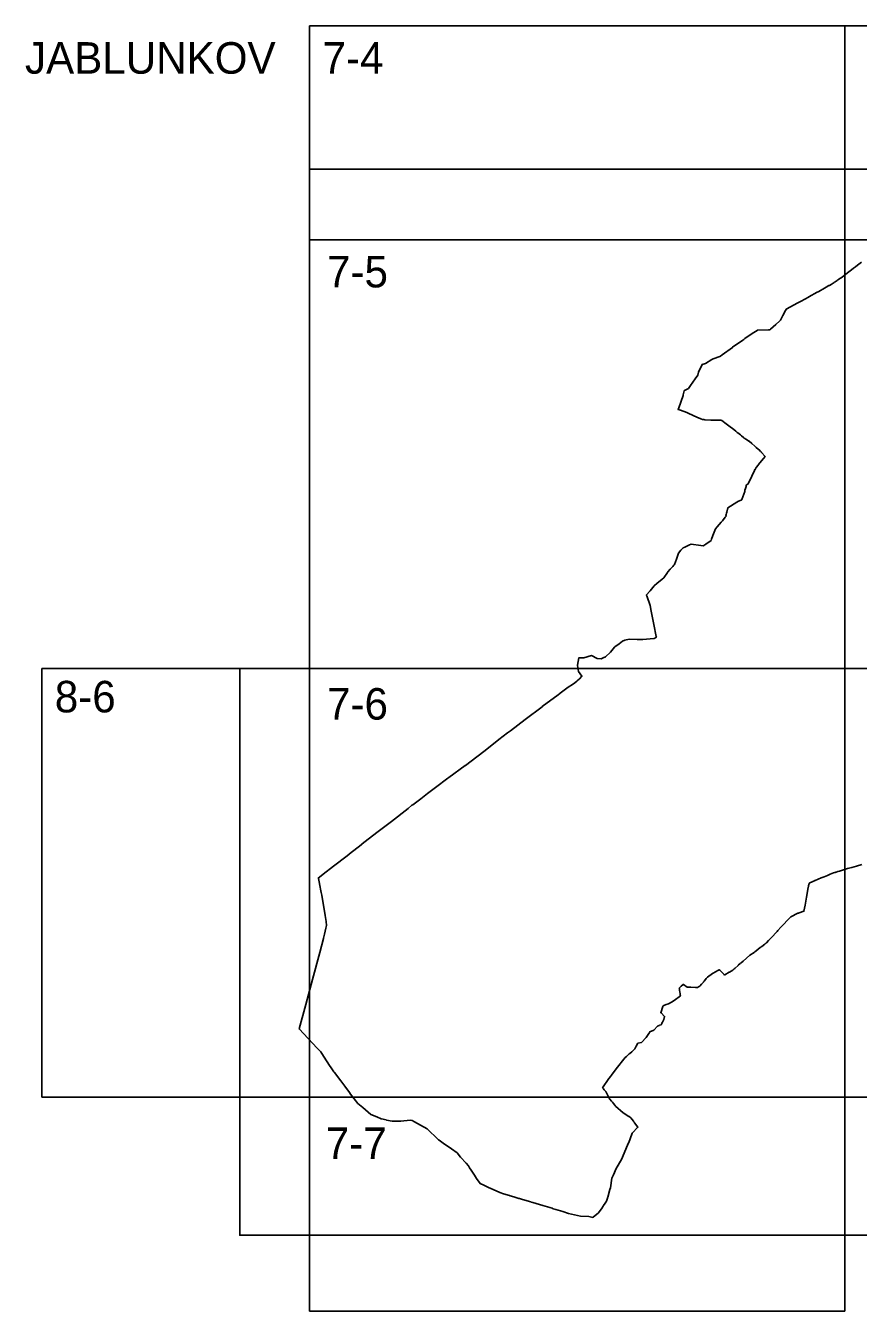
# Model space of a CAD drawing. Extents: x -447352 to -425530, y -1135906 to -1125104.
# Drawn here: x -436845.2 to -436602.1, y -1126653.4 to -1126278.4 of the extents above; entities that cross this region are included whole.
import ezdxf

# ---------------------------------------------------------------- set-up
doc = ezdxf.new("R2010")
doc.units = 0
for name, color, linetype in [('Vrstva 1', 7, 'Continuous'), ('Vrstva 10', 7, 'Continuous'), ('Vrstva 4', 7, 'Continuous')]:
    doc.layers.add(name, color=color, linetype=linetype)

msp = doc.modelspace()

# ---------------------------------------------------------------- linework, layer by layer
at = {"layer": 'Vrstva 1'}
for points in [[(-436601.2, -1126347.4), (-436602.35, -1126348.27), (-436602.92, -1126348.7), (-436603.5, -1126349.14), (-436603.66, -1126349.26), (-436605.79, -1126350.9), (-436606.86, -1126351.72), (-436607.33, -1126352.06), (-436608.09, -1126352.57), (-436608.34, -1126352.73), (-436608.93, -1126353.12), (-436608.97, -1126353.15), (-436609.18, -1126353.29), (-436610.09, -1126353.89), (-436610.1, -1126353.89), (-436610.57, -1126354.15), (-436610.72, -1126354.23), (-436610.9, -1126354.33), (-436611.36, -1126354.58), (-436611.54, -1126354.69), (-436611.7, -1126354.78), (-436611.8, -1126354.84), (-436612.04, -1126354.98), (-436613.7, -1126355.92), (-436613.87, -1126356.01), (-436614.1, -1126356.14), (-436616.57, -1126357.54), (-436616.69, -1126357.61), (-436618.8, -1126358.74), (-436619.82, -1126359.29), (-436623.16, -1126361.1), (-436623.33, -1126361.4), (-436623.39, -1126361.51), (-436624.17, -1126362.97), (-436624.85, -1126364.29), (-436624.99, -1126364.42), (-436625.08, -1126364.5), (-436626.22, -1126365.54), (-436627.73, -1126366.92), (-436627.9, -1126367.07), (-436627.9, -1126367.08), (-436628.37, -1126367.09), (-436631.56, -1126367.18), (-436631.57, -1126367.18), (-436632, -1126367.47), (-436632.83, -1126368.04), (-436635.3, -1126369.7), (-436635.34, -1126369.72), (-436635.58, -1126369.9), (-436635.85, -1126370.1), (-436638.83, -1126372.23), (-436638.9, -1126372.28), (-436641.9, -1126374.46), (-436642.37, -1126374.8), (-436642.53, -1126374.86), (-436644.47, -1126375.58), (-436644.48, -1126375.58), (-436644.87, -1126375.82), (-436646.75, -1126376.98), (-436647.67, -1126377.19), (-436647.92, -1126377.7), (-436648.68, -1126379.21), (-436648.69, -1126379.22), (-436648.76, -1126379.48), (-436648.96, -1126380.32), (-436649.79, -1126381.43), (-436651.16, -1126383.38), (-436651.72, -1126384.19), (-436651.75, -1126384.21), (-436652.91, -1126384.85), (-436653.01, -1126384.91), (-436653.08, -1126385.3), (-436653.23, -1126386.11), (-436653.28, -1126386.3), (-436654.57, -1126389.88), (-436654.74, -1126390.36), (-436654.71, -1126390.35), (-436654.69, -1126390.34), (-436654.01, -1126390.6), (-436652.2, -1126391.26), (-436651.58, -1126391.55), (-436649.29, -1126392.63), (-436649.27, -1126392.63), (-436648.11, -1126393.1), (-436647.64, -1126393.28), (-436647.61, -1126393.29), (-436647.18, -1126393.32), (-436647.04, -1126393.33), (-436646.82, -1126393.35), (-436645.22, -1126393.45), (-436644.18, -1126393.52), (-436643.13, -1126393.49), (-436642.29, -1126393.46), (-436642.28, -1126393.46), (-436642, -1126393.61), (-436641.63, -1126393.87), (-436641.08, -1126394.25), (-436640.69, -1126394.53), (-436639.13, -1126395.67), (-436638.96, -1126395.79), (-436637.85, -1126396.71), (-436637.46, -1126397.03), (-436637.28, -1126397.18), (-436636.53, -1126397.79), (-436636.26, -1126398.02), (-436635.66, -1126398.51), (-436635.44, -1126398.69), (-436634.8, -1126399.11), (-436634.05, -1126399.61), (-436634.02, -1126399.63), (-436633.26, -1126400.31), (-436632.38, -1126401.09), (-436631.94, -1126401.47), (-436630.93, -1126402.36), (-436630.67, -1126402.59), (-436630.62, -1126402.64), (-436630.52, -1126402.74), (-436630.51, -1126402.75), (-436630.42, -1126402.85), (-436630.39, -1126402.88), (-436629.34, -1126404.11), (-436629.35, -1126404.12), (-436629.79, -1126404.61), (-436629.85, -1126404.68), (-436630.42, -1126405.31), (-436631.24, -1126406.37), (-436631.41, -1126406.58), (-436631.97, -1126407.3), (-436632.27, -1126407.83), (-436632.29, -1126407.87), (-436632.3, -1126407.89), (-436632.43, -1126408.17), (-436633.23, -1126409.84), (-436633.54, -1126410.48), (-436634.16, -1126411.77), (-436634.27, -1126412.01), (-436634.28, -1126412.01), (-436634.32, -1126412.04), (-436634.61, -1126412.24), (-436634.69, -1126412.28), (-436634.74, -1126412.38), (-436634.83, -1126412.58), (-436634.92, -1126412.86), (-436635.09, -1126413.42), (-436635.1, -1126413.44), (-436635.22, -1126413.94), (-436635.24, -1126414.01), (-436635.23, -1126414.07), (-436635.22, -1126414.15), (-436635.22, -1126414.22), (-436635.23, -1126414.27), (-436636.11, -1126416.6), (-436636.13, -1126416.65), (-436636.15, -1126416.69), (-436636.16, -1126416.7), (-436636.86, -1126417), (-436637.11, -1126417.11), (-436637.58, -1126417.35), (-436640.19, -1126419.04), (-436640.19, -1126419.04), (-436640.56, -1126420.35), (-436640.64, -1126420.61), (-436640.75, -1126421.03), (-436640.81, -1126421.24), (-436640.81, -1126421.25), (-436640.8, -1126421.25), (-436640.63, -1126421.41), (-436640.64, -1126421.42), (-436641, -1126421.81), (-436641.8, -1126422.81), (-436641.81, -1126422.82), (-436642.02, -1126423.07), (-436642.02, -1126423.08), (-436642.14, -1126423.23), (-436643.3, -1126424.58), (-436643.84, -1126425.21), (-436644.6, -1126427.16), (-436644.98, -1126428.18), (-436645.11, -1126428.53), (-436646.64, -1126429.63), (-436647.26, -1126430.07), (-436647.44, -1126430.11), (-436647.46, -1126430.11), (-436648.09, -1126430.02), (-436650.93, -1126429.6), (-436651.42, -1126429.84), (-436652.75, -1126430.48), (-436653.29, -1126430.74), (-436653.32, -1126430.77), (-436653.75, -1126431.18), (-436653.92, -1126431.4), (-436654.58, -1126432.25), (-436654.58, -1126432.26), (-436655.25, -1126434.06), (-436655.82, -1126435.56), (-436655.82, -1126435.56), (-436655.96, -1126435.78), (-436656.29, -1126436.15), (-436657.01, -1126436.95), (-436657.71, -1126437.72), (-436657.72, -1126437.74), (-436657.85, -1126437.93), (-436658.92, -1126439.5), (-436659.39, -1126439.88), (-436660.96, -1126441.14), (-436661.63, -1126441.68), (-436661.73, -1126441.76), (-436661.76, -1126441.8), (-436662.88, -1126443.23), (-436664.02, -1126444.54), (-436663.87, -1126444.71), (-436663.86, -1126444.74), (-436663.86, -1126444.75), (-436662.85, -1126447.51), (-436662.57, -1126449.17), (-436662.25, -1126451.12), (-436661.84, -1126453.08), (-436661.11, -1126456.58), (-436661.07, -1126456.78), (-436661.72, -1126457.12), (-436661.84, -1126457.19), (-436665.01, -1126457.45), (-436665.17, -1126457.45), (-436666.66, -1126457.42), (-436669.05, -1126457.4), (-436670.33, -1126457.67), (-436670.93, -1126457.94), (-436671.91, -1126458.74), (-436673.21, -1126459.61), (-436673.3, -1126459.72), (-436674.46, -1126461.14), (-436675.91, -1126462.48), (-436676.6, -1126462.8), (-436677.2, -1126463.08), (-436678.37, -1126463.01), (-436679.98, -1126462.16), (-436682.22, -1126462.83), (-436683.7, -1126462.8), (-436684.08, -1126464.91), (-436684.09, -1126464.93), (-436684.1, -1126465.02), (-436683.81, -1126466.83), (-436682.84, -1126468.15), (-436682.83, -1126468.17), (-436683.57, -1126468.92), (-436684.18, -1126469.48), (-436684.43, -1126469.71), (-436685.23, -1126470.34), (-436687.16, -1126471.57), (-436687.22, -1126471.61), (-436689.19, -1126473.14), (-436689.25, -1126473.18), (-436689.74, -1126473.56), (-436694.4, -1126477.02), (-436694.43, -1126477.05), (-436699.38, -1126480.81), (-436703.64, -1126484.06), (-436704.52, -1126484.72), (-436707.09, -1126486.66), (-436711.09, -1126489.79), (-436713.53, -1126491.66), (-436716.84, -1126494.19), (-436716.89, -1126494.23), (-436721.68, -1126497.74), (-436721.91, -1126497.92), (-436725.52, -1126500.6), (-436727.91, -1126502.42), (-436729.88, -1126503.9), (-436732.2, -1126505.65), (-436732.43, -1126505.82), (-436733.56, -1126506.71), (-436738.38, -1126510.51), (-436742.27, -1126513.46), (-436746.49, -1126516.71), (-436747.78, -1126517.71), (-436750.17, -1126519.59), (-436751.35, -1126520.51), (-436755.29, -1126523.56), (-436756.22, -1126524.27), (-436757.46, -1126525.23), (-436759.78, -1126527.03), (-436759.78, -1126527.03), (-436759.74, -1126527.21), (-436759.45, -1126528.59), (-436759.42, -1126528.75), (-436758.89, -1126531.29), (-436758.73, -1126532.02), (-436758.73, -1126532.06), (-436757.8, -1126537.94), (-436757.79, -1126537.97), (-436757.49, -1126539.7), (-436757.49, -1126539.72), (-436757.43, -1126540.09), (-436757.37, -1126540.51), (-436757.4, -1126540.88), (-436757.55, -1126541.61), (-436757.93, -1126543.4), (-436758.22, -1126544.58), (-436758.24, -1126544.63), (-436759.35, -1126548.8), (-436761.45, -1126556.68), (-436763.44, -1126563.9), (-436765.37, -1126571), (-436765.38, -1126571.04), (-436760.1, -1126576.64), (-436759.05, -1126577.77), (-436758.29, -1126578.99), (-436756.27, -1126582.05), (-436756.22, -1126582.12), (-436755.21, -1126583.53), (-436755.05, -1126583.74), (-436753.17, -1126586.22), (-436752.6, -1126586.96), (-436752.57, -1126587), (-436752.05, -1126587.72), (-436750.67, -1126589.62), (-436750.34, -1126590.07), (-436748.19, -1126592.79), (-436746.79, -1126594.01), (-436744.39, -1126595.99), (-436742.65, -1126596.74), (-436741.46, -1126597.26), (-436741.33, -1126597.31), (-436740, -1126597.59), (-436739.86, -1126597.62), (-436738.24, -1126597.95), (-436738.21, -1126597.95), (-436737.25, -1126597.93), (-436736.87, -1126597.93), (-436736.35, -1126597.92), (-436735.67, -1126597.91), (-436734.76, -1126597.87), (-436732.81, -1126597.71), (-436732.36, -1126597.78), (-436731.7, -1126598.13), (-436729.98, -1126599.08), (-436728.02, -1126600.18), (-436727.5, -1126600.66), (-436726.78, -1126601.34), (-436725.98, -1126602.09), (-436724.66, -1126603.39), (-436724.52, -1126603.49), (-436723.33, -1126604.34), (-436720.92, -1126606.05), (-436719.28, -1126607.23), (-436718.23, -1126608.41), (-436716.59, -1126610.23), (-436715.95, -1126610.94), (-436715.59, -1126611.53), (-436715.13, -1126612.27), (-436714.19, -1126613.74), (-436713.56, -1126614.66), (-436712.52, -1126616.1), (-436711.45, -1126616.61), (-436710.07, -1126617.26), (-436708.76, -1126617.87), (-436706.79, -1126618.76), (-436705.66, -1126619.11), (-436703.94, -1126619.68), (-436703.79, -1126619.73), (-436702.7, -1126620.05), (-436701.28, -1126620.47), (-436701.27, -1126620.47), (-436701.06, -1126620.53), (-436701, -1126620.55), (-436700.14, -1126620.81), (-436697.75, -1126621.5), (-436697.63, -1126621.54), (-436697.15, -1126621.68), (-436694.22, -1126622.55), (-436691.53, -1126623.38), (-436691.19, -1126623.48), (-436690.43, -1126623.71), (-436688.42, -1126624.33), (-436686.69, -1126624.88), (-436683.23, -1126625.62)], [(-436683.23, -1126625.62), (-436680.84, -1126625.81), (-436679.64, -1126626.04), (-436679.53, -1126625.95), (-436677.95, -1126624.68), (-436676.92, -1126623.2), (-436676.81, -1126623.05), (-436676.29, -1126622.29), (-436676.18, -1126622.12), (-436676.04, -1126621.89), (-436675.66, -1126621.26), (-436675.39, -1126620.43), (-436675.37, -1126620.36), (-436675.35, -1126620.31), (-436675.32, -1126620.2), (-436675.29, -1126620.11), (-436675.29, -1126620.1), (-436674.66, -1126617.9), (-436674.52, -1126617.38), (-436674.07, -1126614.63), (-436674.07, -1126614.63), (-436673.88, -1126614.19), (-436673.62, -1126613.57), (-436672.83, -1126611.74), (-436671.26, -1126609.09), (-436669.51, -1126604.96), (-436669.19, -1126604.32), (-436669.15, -1126604.19), (-436668.76, -1126603.09), (-436668.17, -1126601.42), (-436666.49, -1126599.71), (-436667.42, -1126598.47), (-436667.48, -1126598.38), (-436667.53, -1126598.32), (-436667.56, -1126598.28), (-436667.63, -1126598.18), (-436667.68, -1126598.1), (-436667.76, -1126597.98), (-436668.12, -1126597.46), (-436668.49, -1126597), (-436669.06, -1126596.63), (-436669.16, -1126596.57), (-436670.81, -1126595.5), (-436673, -1126593.56), (-436673.13, -1126593.39), (-436673.16, -1126593.35), (-436673.24, -1126593.25), (-436673.58, -1126592.83), (-436673.91, -1126592.42), (-436674.17, -1126592.1), (-436674.65, -1126591.51), (-436674.73, -1126591.41), (-436675.23, -1126590.45), (-436675.52, -1126589.89), (-436675.75, -1126589.46), (-436675.8, -1126589.37), (-436675.84, -1126589.32), (-436676.1, -1126589.03), (-436676.3, -1126588.8), (-436676.56, -1126588.51), (-436676.78, -1126588.26), (-436674.92, -1126585.52), (-436674.83, -1126585.4), (-436674.51, -1126584.95), (-436674.19, -1126584.51), (-436672.86, -1126582.68), (-436670.18, -1126579.42), (-436669.83, -1126579.1), (-436669.12, -1126578.4), (-436669.01, -1126578.31), (-436668.82, -1126578.17), (-436668.22, -1126577.69), (-436667.36, -1126576.85), (-436666.95, -1126576.09), (-436666.48, -1126575.22), (-436665.43, -1126574.98), (-436664.03, -1126573.55), (-436663.49, -1126572.7), (-436663.48, -1126572.69), (-436663.48, -1126572.67), (-436663.27, -1126572.34), (-436663.22, -1126572.26), (-436662.98, -1126571.87), (-436661.82, -1126571.43), (-436660.8, -1126570.25), (-436660.27, -1126570.05), (-436660.15, -1126570), (-436659.73, -1126569.84), (-436659.51, -1126569.45), (-436659.46, -1126569.36), (-436659.29, -1126569.06), (-436658.88, -1126568.32), (-436658.68, -1126567.41), (-436658.68, -1126567.39), (-436658.67, -1126567.38), (-436659.72, -1126566.39), (-436659.74, -1126566.38), (-436659.75, -1126566.36), (-436659.8, -1126566.32), (-436659.15, -1126564.52), (-436659.08, -1126564.32), (-436658.92, -1126564.26), (-436658.19, -1126563.97), (-436657.5, -1126563.7), (-436657.38, -1126563.65), (-436656.17, -1126562.94), (-436656.05, -1126562.86), (-436656.05, -1126562.86), (-436656.04, -1126562.85), (-436655.92, -1126562.78), (-436654.06, -1126561.38), (-436654.06, -1126561.34), (-436654.09, -1126561.18), (-436654.16, -1126560.7), (-436654.22, -1126560.35), (-436654.32, -1126559.73), (-436654.34, -1126559.62), (-436654.36, -1126559.49), (-436654.38, -1126559.32), (-436654.41, -1126559.18), (-436653.87, -1126558.62), (-436653.31, -1126558.05), (-436653.27, -1126558), (-436653.13, -1126558.1), (-436652.13, -1126558.89), (-436651.45, -1126558.9), (-436651.39, -1126558.9), (-436651.14, -1126558.91), (-436650.98, -1126558.91), (-436649.67, -1126558.93), (-436649.04, -1126558.95), (-436648.77, -1126558.79), (-436648.74, -1126558.77), (-436648.62, -1126558.7), (-436648.48, -1126558.61), (-436648.44, -1126558.58), (-436647.9, -1126557.98), (-436647.79, -1126557.86), (-436647.7, -1126557.76), (-436647.53, -1126557.58), (-436647.45, -1126557.49), (-436647.34, -1126557.37), (-436647.31, -1126557.33), (-436647.28, -1126557.3), (-436647.23, -1126557.24), (-436647.14, -1126557.13), (-436646.74, -1126556.63), (-436646.53, -1126556.37), (-436646.28, -1126556.05), (-436646.17, -1126555.97), (-436644.71, -1126554.9), (-436644.5, -1126554.77), (-436643.14, -1126554), (-436642.74, -1126553.77), (-436642.74, -1126553.77), (-436642.6, -1126553.92), (-436641.89, -1126554.63), (-436641.52, -1126555.01), (-436641.34, -1126555.18), (-436641.19, -1126555.33), (-436641.1, -1126555.29), (-436639.82, -1126554.52), (-436639.73, -1126554.47), (-436638.8, -1126553.91), (-436638.76, -1126553.88), (-436638.43, -1126553.59), (-436638.38, -1126553.55), (-436638.21, -1126553.4), (-436638.2, -1126553.39), (-436638.2, -1126553.39), (-436638.16, -1126553.35), (-436638.12, -1126553.31), (-436637.23, -1126552.5), (-436637.21, -1126552.49), (-436636.62, -1126551.95), (-436636.51, -1126551.86), (-436636.4, -1126551.76), (-436636.4, -1126551.76), (-436636.39, -1126551.76), (-436636.39, -1126551.76), (-436636.39, -1126551.75), (-436636.38, -1126551.75), (-436636.37, -1126551.74), (-436636.37, -1126551.74), (-436636.36, -1126551.73), (-436636.36, -1126551.73), (-436636.35, -1126551.73), (-436636.35, -1126551.73), (-436635.77, -1126551.24), (-436633.78, -1126549.56), (-436632.58, -1126548.71), (-436632.46, -1126548.63), (-436632.41, -1126548.59), (-436632.39, -1126548.58), (-436632.34, -1126548.55), (-436631.98, -1126548.28), (-436630.74, -1126547.34), (-436630.56, -1126547.2), (-436630.35, -1126547.04), (-436630.33, -1126547.02), (-436629.45, -1126546.35), (-436629.1, -1126546.08), (-436629.05, -1126546.02), (-436628.96, -1126545.92), (-436628.32, -1126545.24), (-436627.42, -1126544.26), (-436626.06, -1126542.85), (-436625.84, -1126542.62), (-436625.59, -1126542.34), (-436624.75, -1126541.39), (-436624.46, -1126541.07), (-436624.26, -1126540.86), (-436623.97, -1126540.54), (-436622.79, -1126539.35), (-436621.86, -1126538.33), (-436619.8, -1126537.32), (-436619.64, -1126537.27), (-436619.44, -1126537.19), (-436618, -1126536.7), (-436617.85, -1126535.83), (-436617.69, -1126534.96), (-436617.27, -1126532.59), (-436617.19, -1126532.12), (-436616.86, -1126530.24), (-436616.66, -1126529.36), (-436616.63, -1126529.24), (-436616.58, -1126529.05), (-436616.57, -1126529.01), (-436616.55, -1126528.94), (-436616.54, -1126528.9), (-436616.53, -1126528.85), (-436616.52, -1126528.81), (-436616.51, -1126528.79), (-436616.45, -1126528.58), (-436615.37, -1126528.04), (-436615.08, -1126527.9), (-436615.06, -1126527.89), (-436614.81, -1126527.76), (-436614.76, -1126527.74), (-436612.99, -1126527.02), (-436612.96, -1126527.01), (-436612.93, -1126526.99), (-436612.13, -1126526.68), (-436611.17, -1126526.28), (-436610.36, -1126525.94), (-436609.42, -1126525.55), (-436609.34, -1126525.52), (-436608.73, -1126525.28), (-436608.88, -1126525.44), (-436608.64, -1126525.35), (-436608.15, -1126525.15), (-436607.62, -1126524.99), (-436605.92, -1126524.47), (-436605.33, -1126524.3), (-436604.88, -1126524.18), (-436603.99, -1126523.93), (-436602.68, -1126523.55), (-436601.14, -1126523.09)]]:
    msp.add_lwpolyline(points, dxfattribs=at)
at = {"layer": 'Vrstva 10'}
msp.add_lwpolyline([(-436449.84, -1126320.23), (-436449.84, -1126631.21), (-436782.71, -1126631.21), (-436782.71, -1126465.91), (-436762.34, -1126465.91), (-436762.34, -1126340.91), (-436762.34, -1126320.23), (-436449.84, -1126320.23)], dxfattribs=at)
at = {"layer": 'Vrstva 4'}
for p, q in [((-436762.34, -1126278.41), (-436449.84, -1126278.41)), ((-436840.47, -1126465.91), (-436840.47, -1126590.91)), ((-436762.34, -1126653.41), (-436606.09, -1126653.41))]:
    msp.add_line(p, q, dxfattribs=at)
for points in [[(-436606.09, -1126278.41), (-436606.09, -1126340.91), (-436762.34, -1126340.91), (-436762.34, -1126278.41)], [(-436449.84, -1126278.41), (-436449.84, -1126340.91), (-436606.09, -1126340.91), (-436606.09, -1126278.41)], [(-436840.47, -1126465.91), (-436762.34, -1126465.91), (-436762.34, -1126590.91), (-436840.47, -1126590.91)], [(-436762.34, -1126653.41), (-436762.34, -1126590.91), (-436606.09, -1126590.91), (-436606.09, -1126653.41)]]:
    msp.add_lwpolyline(points, dxfattribs=at)
for points in [[(-436606.09, -1126340.91), (-436606.09, -1126465.91), (-436762.34, -1126465.91), (-436762.34, -1126340.91)], [(-436449.84, -1126340.91), (-436449.84, -1126465.91), (-436606.09, -1126465.91), (-436606.09, -1126340.91)], [(-436606.09, -1126465.91), (-436606.09, -1126590.91), (-436762.34, -1126590.91), (-436762.34, -1126465.91)], [(-436449.84, -1126465.91), (-436449.84, -1126590.91), (-436606.09, -1126590.91), (-436606.09, -1126465.91)]]:
    msp.add_lwpolyline(points, close=True, dxfattribs=at)

# ---------------------------------------------------------------- texts
at = {"layer": 'Vrstva 1'}
for s, p in [('JABLUNKOV', (-436845.38, -1126292.41)), ('7-4', (-436758.53, -1126292.41)), ('7-5', (-436757.22, -1126354.75)), ('8-6', (-436836.69, -1126478.72)), ('7-6', (-436757.22, -1126480.82)), ('7-7', (-436757.58, -1126608.99))]:
    msp.add_text(s, height=9.2, dxfattribs=at).set_placement(p)

doc.saveas('drawing.dxf')
